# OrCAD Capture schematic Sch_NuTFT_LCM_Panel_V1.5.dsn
size A4; title: NuTFT LCM Panel; rev: V1.5
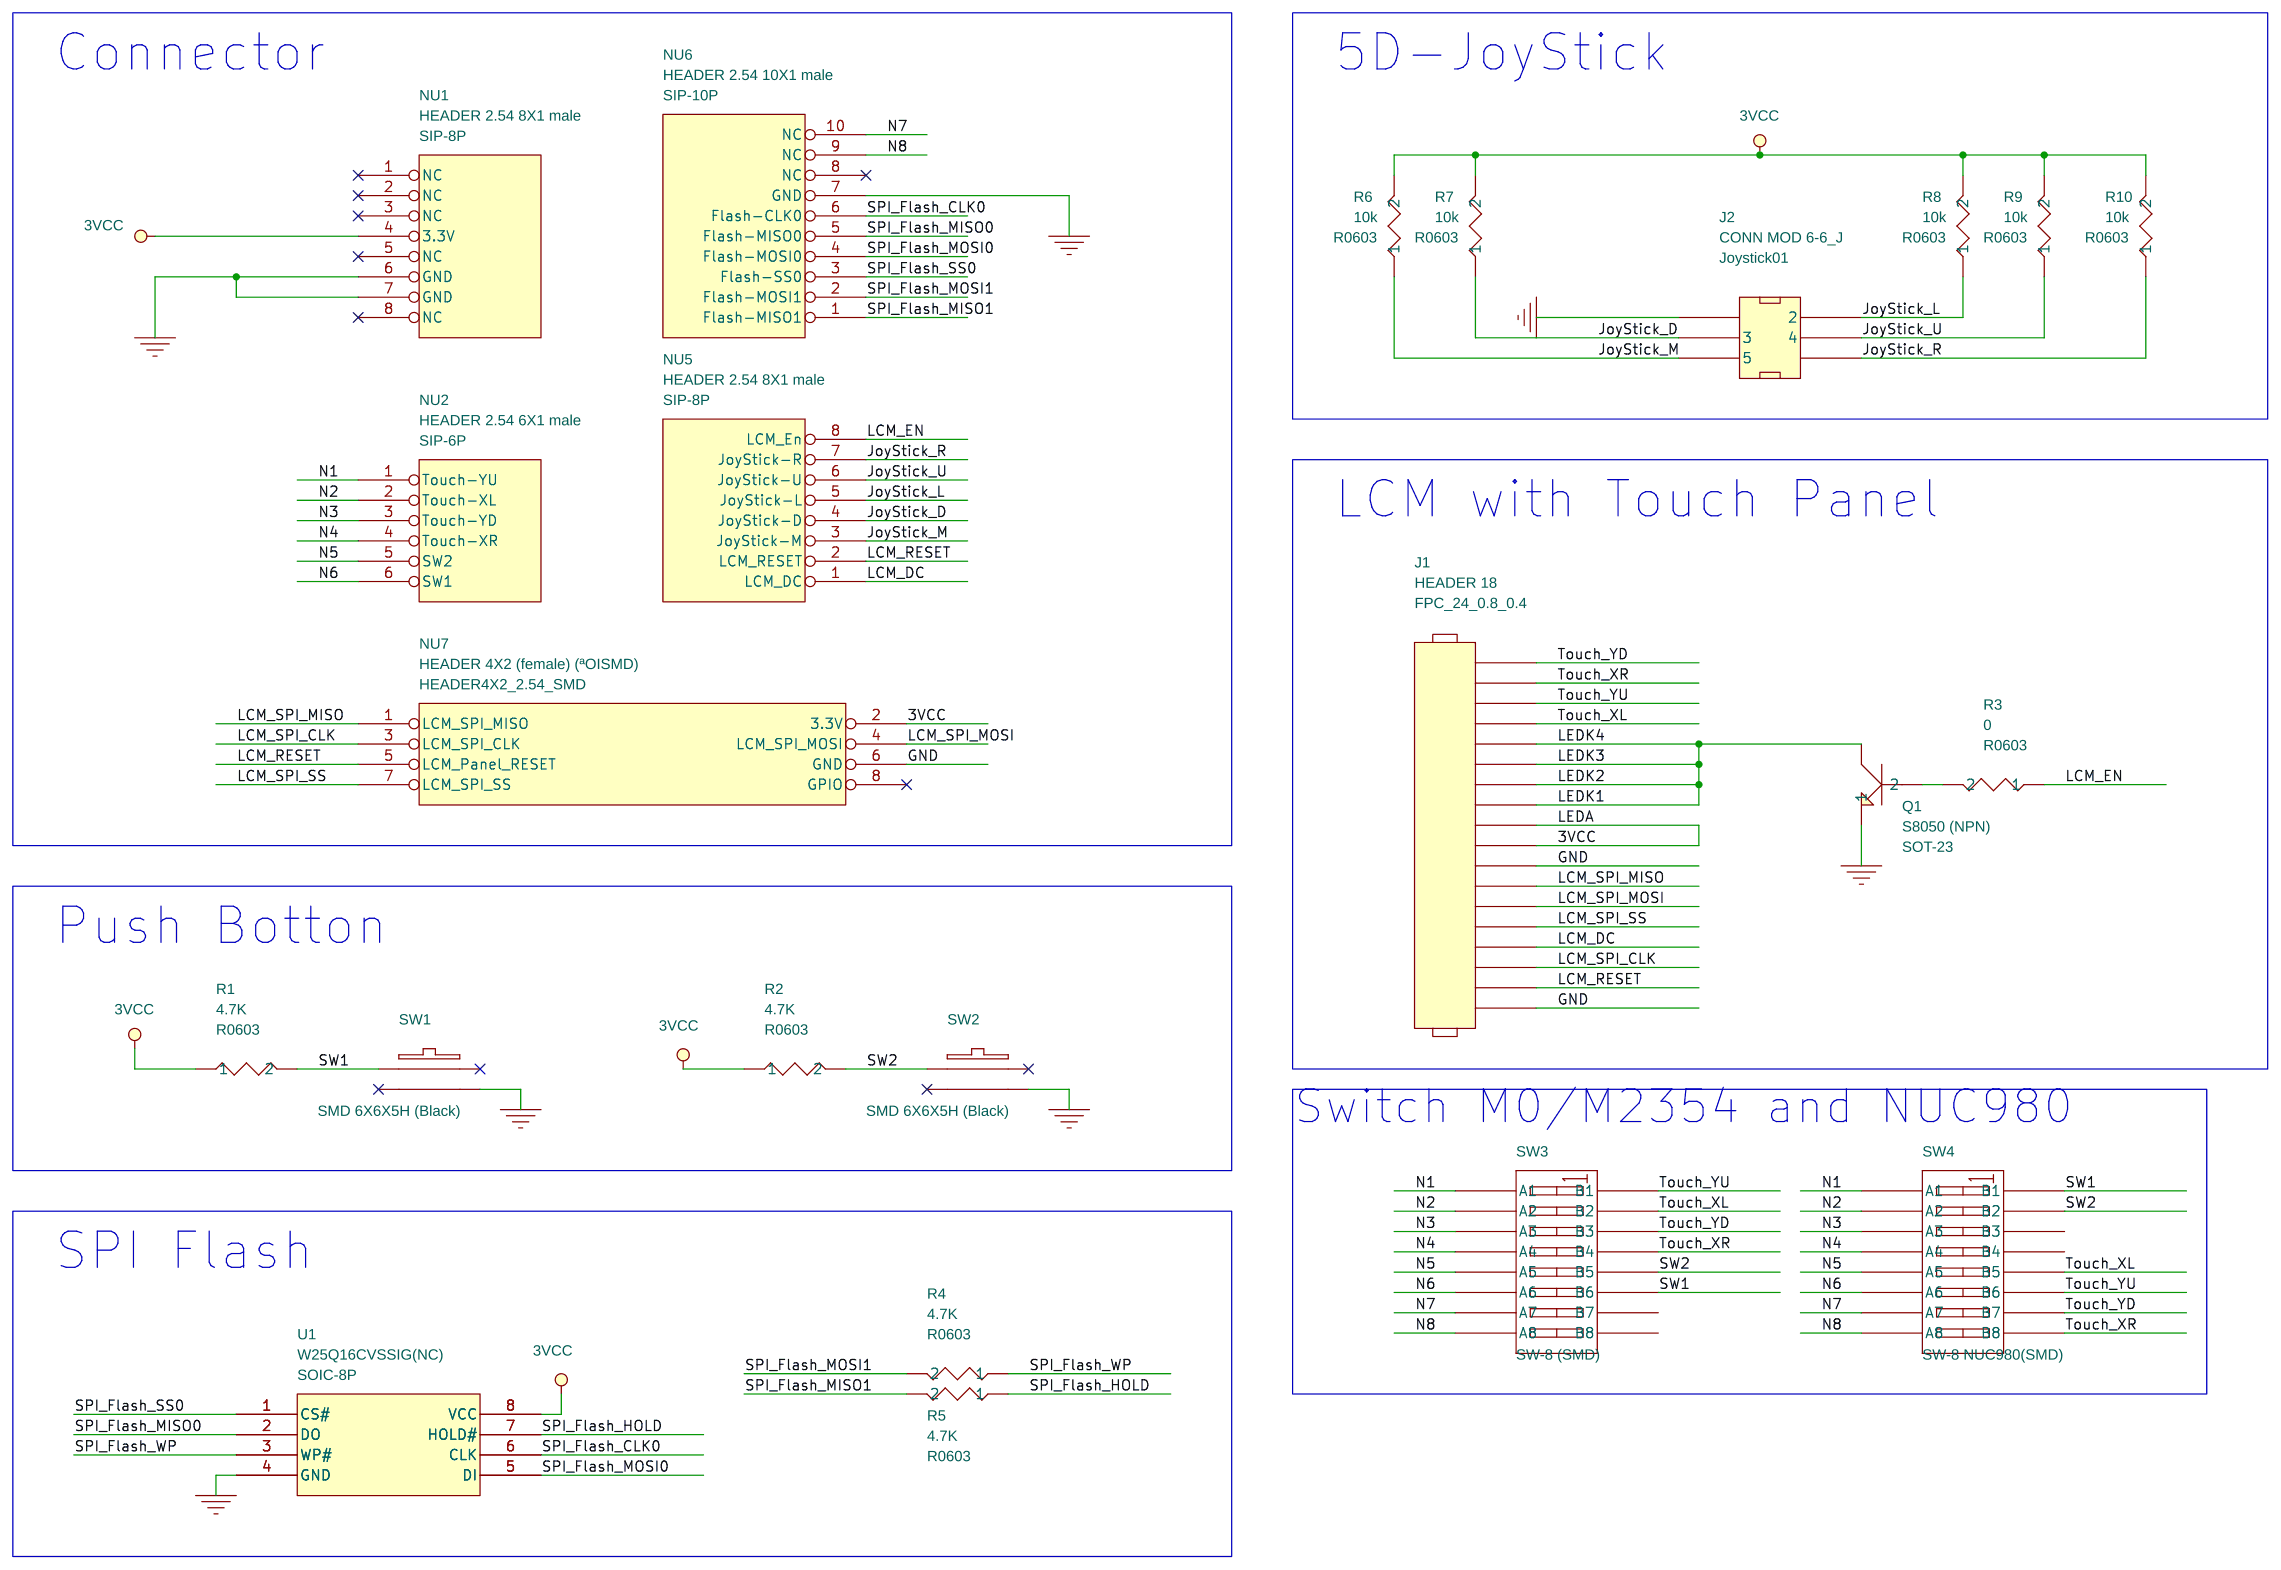
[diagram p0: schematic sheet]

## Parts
J1  HEADER 18  [FPC_24_0.8_0.4]
J2  CONN MOD 6-6_J  [Joystick01]
NU1  HEADER 2.54 8X1 male  [SIP-8P]
NU2  HEADER 2.54 6X1 male  [SIP-6P]
NU5  HEADER 2.54 8X1 male  [SIP-8P]
NU6  HEADER 2.54 10X1 male  [SIP-10P]
NU7  HEADER 4X2 (female) (ªO­ISMD)  [HEADER4X2_2.54_SMD]
Q1  S8050 (NPN)  [SOT-23]
R1  4.7K  [R0603]
R2  4.7K  [R0603]
R3  0  [R0603]
R4  4.7K  [R0603]
R5  4.7K  [R0603]
R6  10k  [R0603]
R7  10k  [R0603]
R8  10k  [R0603]
R9  10k  [R0603]
R10  10k  [R0603]
SW1  SMD 6X6X5H (Black)  [STS-B5]
SW2  SMD 6X6X5H (Black)  [STS-B5]
SW3  SW-8 (SMD)  [SWDIP-8/SMD]
SW4  SW-8 NUC980(SMD)  [SWDIP-8/SMD]
U1  W25Q16CVSSIG(NC)  [SOIC-8P]

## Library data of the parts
J1 = HEADER_18
J2 = CONN_MOD_6-6_J
NU1 = POWER_CONNECT_0
NU2 = ADC_CONNECT_2
NU5 = PWM0_CONNECT_3
NU6 = PWM1_CONNECT_1
NU7 = SPI_CONNECT_2
Q1 = NPN_2
R1 = R_4: Package: 0603
R2 = R_2: Package: 0603
R3 = R_1: Package: 0603
R4 = R_3: Package: 0603
R5 = R: Package: 0603
R6 = R_0_3: Package: 0603
R7 = R_0_2: Package: 0603
R8 = R_0: Package: 0603
R9 = R_0_4: Package: 0603
R10 = R_0_1: Package: 0603
SW1 = SW-S_1
SW2 = SW-S
SW3 SW4 = SW_DIP-8
U1 = W25P10_20_40_SOIC_0: Package: SOP8; Vendor: WINBOND

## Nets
3VCC: J1.9 J1.10 NU1.4(3.3V) NU7.2(3.3V) R1.1 R2.1 R6.2 R7.2 R8.2 R9.2 R10.2 U1.8(VCC)
GND: J1.1 J1.8 J2.1 NU1.6(GND) NU1.7(GND) NU6.7(GND) NU7.6(GND) Q1.2(1) SW1.2 SW2.2 U1.4(GND)
JoyStick_D: J2.2(3) NU5.4(JoyStick-D) R7.1
JoyStick_L: J2.4(2) NU5.5(JoyStick-L) R8.1
JoyStick_M: J2.3(5) NU5.3(JoyStick-M) R6.1
JoyStick_R: J2.6 NU5.7(JoyStick-R) R10.1
JoyStick_U: J2.5(4) NU5.6(JoyStick-U) R9.1
LCM_DC: J1.4 NU5.1(LCM_DC)
LCM_EN: NU5.8(LCM_En) R3.1
LCM_RESET: J1.2 NU5.2(LCM_RESET) NU7.5(LCM_Panel_RESET)
LCM_SPI_CLK: J1.3 NU7.3(LCM_SPI_CLK)
LCM_SPI_MISO: J1.7 NU7.1(LCM_SPI_MISO)
LCM_SPI_MOSI: J1.6 NU7.4(LCM_SPI_MOSI)
LCM_SPI_SS: J1.5 NU7.7(LCM_SPI_SS)
LEDK1: J1.11 J1.12 J1.13 J1.14 Q1.3
N1: NU2.1(Touch-YU) SW3.1(A1) SW4.1(A1)
N2: NU2.2(Touch-XL) SW3.2(A2) SW4.2(A2)
N3: NU2.3(Touch-YD) SW3.3(A3) SW4.3(A3)
N4: NU2.4(Touch-XR) SW3.4(A4) SW4.4(A4)
N5: NU2.5(SW2) SW3.5(A5) SW4.5(A5)
N6: NU2.6(SW1) SW3.6(A6) SW4.6(A6)
N7: NU6.10(NC) SW3.7(A7) SW4.7(A7)
N8: NU6.9(NC) SW3.8(A8) SW4.8(A8)
SPI_Flash_CLK0: NU6.6(Flash-CLK0) U1.6(CLK)
SPI_Flash_HOLD: R5.1 U1.7(HOLD#)
SPI_Flash_MISO0: NU6.5(Flash-MISO0) U1.2(DO)
SPI_Flash_MISO1: NU6.1(Flash-MISO1) R5.2
SPI_Flash_MOSI0: NU6.4(Flash-MOSI0) U1.5(DI)
SPI_Flash_MOSI1: NU6.2(Flash-MOSI1) R4.2
SPI_Flash_SS0: NU6.3(Flash-SS0) U1.1(CS#)
SPI_Flash_WP: R4.1 U1.3(WP#)
SW1: R1.2 SW1.3 SW3.11(B6) SW4.16(B1)
SW2: R2.2 SW2.3 SW3.12(B5) SW4.15(B2)
Touch_XL: J1.15 SW3.15(B2) SW4.12(B5)
Touch_XR: J1.17 SW3.13(B4) SW4.9(B8)
Touch_YD: J1.18 SW3.14(B3) SW4.10(B7)
Touch_YU: J1.16 SW3.16(B1) SW4.11(B6)
N17555519: Q1.1(2) R3.2

Not connected (* = marked no-connect by the designer): NU1 1(NC)* 2(NC)* 3(NC)* 5(NC)* 8(NC)*; NU6 8(NC)*; NU7 8(GPIO)*; SW1 1* 4*; SW2 1* 4*; SW3 9(B8) 10(B7); SW4 13(B4) 14(B3)

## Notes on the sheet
- Connector
- 5D-JoyStick
- LCM with Touch Panel
- Push Botton
- Switch M0/M2354 and NUC980
- SPI Flash
